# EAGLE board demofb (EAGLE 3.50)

Size 71.12 x 68.58 mm. Coordinates in mm from the lower left corner, seen from the top.
Outline: 0,0 71.12,0 71.12,68.58 0,68.58 0,0
Copper layers used: 
tRestrict: area 26.7,0 to 44.5,8.9

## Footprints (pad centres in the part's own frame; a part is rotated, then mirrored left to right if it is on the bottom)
10 = drill 0.813 pad 1.397 octagon:  -5.08,0;  5.08,0
L28 = drill 0.813 pad 1.397 octagon:  -15.24,-7.62;  -12.7,-7.62;  -10.16,-7.62;  -7.62,-7.62;  -5.08,-7.62;  -2.54,-7.62;  0,-7.62;  2.54,-7.62;  5.08,-7.62;  7.62,-7.62;  10.16,-7.62;  12.7,-7.62;  15.24,-7.62;  17.78,-7.62;  17.78,7.62;  15.24,7.62;  12.7,7.62;  10.16,7.62;  7.62,7.62;  5.08,7.62;  2.54,7.62;  0,7.62;  -2.54,7.62;  -5.08,7.62;  -7.62,7.62;  -10.16,7.62;  -12.7,7.62;  -15.24,7.62
L40 = drill 0.813 pad 1.397 octagon:  -21.59,-7.62;  -19.05,-7.62;  -16.51,-7.62;  -13.97,-7.62;  -11.43,-7.62;  -8.89,-7.62;  -6.35,-7.62;  -3.81,-7.62;  -1.27,-7.62;  1.27,-7.62;  3.81,-7.62;  6.35,-7.62;  8.89,-7.62;  11.43,-7.62;  13.97,-7.62;  16.51,-7.62;  19.05,-7.62;  21.59,-7.62;  24.13,-7.62;  26.67,-7.62;  26.67,7.62;  24.13,7.62;  21.59,7.62;  19.05,7.62;  16.51,7.62;  13.97,7.62;  11.43,7.62;  8.89,7.62;  6.35,7.62;  3.81,7.62;  1.27,7.62;  -1.27,7.62;  -3.81,7.62;  -6.35,7.62;  -8.89,7.62;  -11.43,7.62;  -13.97,7.62;  -16.51,7.62;  -19.05,7.62;  -21.59,7.62
L24 = drill 0.813 pad 1.397 octagon:  -13.97,-7.62;  -11.43,-7.62;  -8.89,-7.62;  -6.35,-7.62;  -3.81,-7.62;  -1.27,-7.62;  1.27,-7.62;  3.81,-7.62;  6.35,-7.62;  8.89,-7.62;  11.43,-7.62;  13.97,-7.62;  13.97,7.62;  11.43,7.62;  8.89,7.62;  6.35,7.62;  3.81,7.62;  1.27,7.62;  -1.27,7.62;  -3.81,7.62;  -6.35,7.62;  -8.89,7.62;  -11.43,7.62;  -13.97,7.62
L8 = drill 0.813 pad 1.397 octagon:  -3.81,-3.81;  -1.27,-3.81;  1.27,-3.81;  3.81,-3.81;  3.81,3.81;  1.27,3.81;  -1.27,3.81;  -3.81,3.81
18 = drill 0.813 pad 1.397 octagon:  -21.59,0;  -19.05,0;  -16.51,0;  -13.97,0;  -11.43,0;  -8.89,0;  -6.35,0;  -3.81,0;  -1.27,0;  1.27,0;  3.81,0;  6.35,0;  8.89,0;  11.43,0;  13.97,0;  16.51,0;  19.05,0;  21.59,0
 = drill 0.813 pad 1.397 octagon:  -2.54,0;  2.54,0
L14 = drill 0.813 pad 1.397 octagon:  -7.62,-3.81;  -5.08,-3.81;  -2.54,-3.81;  0,-3.81;  2.54,-3.81;  5.08,-3.81;  7.62,-3.81;  7.62,3.81;  5.08,3.81;  2.54,3.81;  0,3.81;  -2.54,3.81;  -5.08,3.81;  -7.62,3.81

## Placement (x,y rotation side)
C1  0.1u  [10]  34.29,60.96 270 top
C2  33p  [10]  44.45,60.96 90 top
D1  1N4148  [10]  21.59,8.89 270 top
IC1  6504  [L28]  39.37,40.64 270 top
IC2  6532  [L40]  19.05,44.45 270 top
IC3  2716  [L24]  58.42,41.91 270 top
IC4  555  [L8]  50.8,7.62 270 top
J1  1X18  [18]  5.08,26.67 270 top
QU1  1MHz  []  54.61,63.5 180 top
R1  330k  [10]  63.5,60.96 270 top
R2  2.2M  [10]  11.43,7.62 270 top
R3  3.3k  [10]  16.51,7.62 270 top
U1  7400  [L14]  62.23,11.43 270 top

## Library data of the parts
C1 C2 D1 IC1-IC4 J1 QU1 R1-R3 U1 = DEMO

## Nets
A0: IC1. IC2. IC3.
A1: IC1. IC2. IC3.
A2: IC1. IC2. IC3.
A3: IC1. IC2. IC3.
A4: IC1. IC2. IC3.
A5: IC1. IC2. IC3.
A6: IC1. IC2. IC3.
A7: IC1. IC3.
A8: IC1. IC3.
A9: IC1. IC3.
D0: IC1. IC2. IC3.
D1: IC1. IC2. IC3.
D2: IC1. IC2. IC3.
D3: IC1. IC2. IC3.
D4: IC1. IC2. IC3.
D5: IC1. IC2. IC3.
D6: IC1. IC2. IC3.
D7: IC1. IC2. IC3.
GND: C1. IC1. IC2. IC3. IC4. J1. U1.
N$1: C2. D1. IC1. QU1. R1.
N$4: C2. IC1. U1.
N$7: IC1. IC2. U1.
N$11: C1. IC4. R2.
N$13: IC4. U1.
N$15: IC3. U1.
N$19: IC1. IC2. U1.
N$20: IC1. IC2. U1.
N$23: IC1. IC2.
N$24: IC2. U1.
N$27: QU1. R1. U1.
N$28: IC1. IC2. R3.
N$29: IC2. J1.
N$30: IC2. J1.
N$31: IC2. J1.
N$32: IC2. J1.
N$33: IC2. J1.
N$34: IC2. J1.
N$35: IC2. J1.
N$36: IC2. J1.
N$37: IC2. J1.
N$38: IC2. J1.
N$39: IC2. J1.
N$40: IC2. J1.
N$41: IC2. J1.
N$42: IC2. J1.
N$43: IC2. J1.
N$44: IC2. J1.
VCC: D1. IC1. IC2. IC3. IC4. J1. R2. R3. U1.

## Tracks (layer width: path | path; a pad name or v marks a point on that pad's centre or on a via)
A0  (2 unrouted)
A1  (2 unrouted)
A2  (2 unrouted)
A3  (2 unrouted)
A4  (2 unrouted)
A5  (2 unrouted)
A6  (2 unrouted)
A7  (1 unrouted)
A8  (1 unrouted)
A9  (1 unrouted)
D0  (2 unrouted)
D1  (2 unrouted)
D2  (2 unrouted)
D3  (2 unrouted)
D4  (2 unrouted)
D5  (2 unrouted)
D6  (2 unrouted)
D7  (2 unrouted)
GND  (8 unrouted)
N$1  (4 unrouted)
N$4  (3 unrouted)
N$7  (2 unrouted)
N$11  (3 unrouted)
N$13  (2 unrouted)
N$15  (1 unrouted)
N$19  (2 unrouted)
N$20  (2 unrouted)
N$23  (1 unrouted)
N$24  (1 unrouted)
N$27  (4 unrouted)
N$28  (2 unrouted)
N$29  (1 unrouted)
N$30  (1 unrouted)
N$31  (1 unrouted)
N$32  (1 unrouted)
N$33  (1 unrouted)
N$34  (1 unrouted)
N$35  (1 unrouted)
N$36  (1 unrouted)
N$37  (1 unrouted)
N$38  (1 unrouted)
N$39  (1 unrouted)
N$40  (1 unrouted)
N$41  (1 unrouted)
N$42  (1 unrouted)
N$43  (1 unrouted)
N$44  (1 unrouted)
VCC  (11 unrouted)

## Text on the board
Top: by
